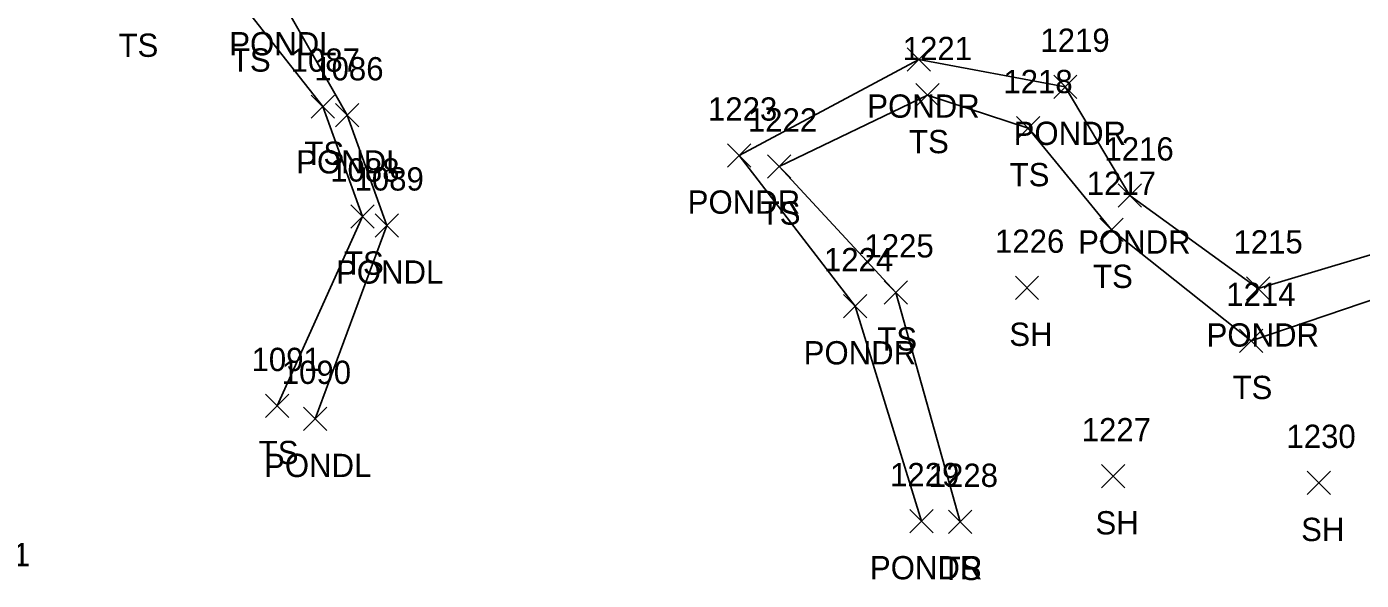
# Model space of a CAD drawing. Extents: x 1497084 to 1499861, y 734741 to 735567.
# Drawn here: x 1498306.3 to 1498420.9, y 735223.2 to 735270.8 of the extents above; entities that cross this region are included whole.
import ezdxf

# ---------------------------------------------------------------- set-up
doc = ezdxf.new("R2010")
doc.units = 0
for name, color, linetype in [('L_A', 7, 'Continuous'), ('L_I', 7, 'Continuous'), ('L_TIC', 7, 'Continuous'), ('LAWE', 7, 'Continuous'), ('LELB', 7, 'Continuous')]:
    doc.layers.add(name, color=color, linetype=linetype)

msp = doc.modelspace()

# ---------------------------------------------------------------- linework, layer by layer
at = {"layer": 'L_TIC'}
for points in [[(1498381.91, 735266.99), (1498383.91, 735268.99)], [(1498383.91, 735266.99), (1498381.91, 735268.99)], [(1498394.49, 735264.65), (1498396.49, 735266.65)], [(1498396.49, 735264.65), (1498394.49, 735266.65)], [(1498382.66, 735263.94), (1498384.66, 735265.94)], [(1498384.66, 735263.94), (1498382.66, 735265.94)], [(1498330.73, 735262.94), (1498332.73, 735264.94)], [(1498332.73, 735262.94), (1498330.73, 735264.94)], [(1498332.81, 735262.2), (1498334.81, 735264.2)], [(1498334.81, 735262.2), (1498332.81, 735264.2)], [(1498391.3, 735261.1), (1498393.3, 735263.1)], [(1498393.3, 735261.1), (1498391.3, 735263.1)], [(1498366.49, 735258.74), (1498368.49, 735260.74)], [(1498368.49, 735258.74), (1498366.49, 735260.74)], [(1498369.92, 735257.8), (1498371.92, 735259.8)], [(1498371.92, 735257.8), (1498369.92, 735259.8)], [(1498400.03, 735255.31), (1498402.03, 735257.31)], [(1498402.03, 735255.31), (1498400.03, 735257.31)], [(1498334.13, 735253.5), (1498336.13, 735255.5)], [(1498336.13, 735253.5), (1498334.13, 735255.5)], [(1498336.23, 735252.73), (1498338.23, 735254.73)], [(1498338.23, 735252.73), (1498336.23, 735254.73)], [(1498398.46, 735252.36), (1498400.46, 735254.36)], [(1498400.46, 735252.36), (1498398.46, 735254.36)], [(1498391.2, 735247.38), (1498393.2, 735249.38)], [(1498393.2, 735247.38), (1498391.2, 735249.38)], [(1498411.05, 735247.32), (1498413.05, 735249.32)], [(1498413.05, 735247.32), (1498411.05, 735249.32)], [(1498379.93, 735246.98), (1498381.93, 735248.98)], [(1498381.93, 735246.98), (1498379.93, 735248.98)], [(1498376.45, 735245.79), (1498378.45, 735247.79)], [(1498378.45, 735245.79), (1498376.45, 735247.79)], [(1498410.44, 735242.81), (1498412.44, 735244.81)], [(1498412.44, 735242.81), (1498410.44, 735244.81)], [(1498326.81, 735237.22), (1498328.81, 735239.22)], [(1498328.81, 735237.22), (1498326.81, 735239.22)], [(1498330.06, 735236.11), (1498332.06, 735238.11)], [(1498332.06, 735236.11), (1498330.06, 735238.11)], [(1498398.59, 735231.18), (1498400.59, 735233.18)], [(1498400.59, 735231.18), (1498398.59, 735233.18)], [(1498416.26, 735230.61), (1498418.26, 735232.61)], [(1498418.26, 735230.61), (1498416.26, 735232.61)], [(1498382.14, 735227.32), (1498384.14, 735229.32)], [(1498384.14, 735227.32), (1498382.14, 735229.32)], [(1498385.46, 735227.26), (1498387.46, 735229.26)], [(1498387.46, 735227.26), (1498385.46, 735229.26)]]:
    msp.add_lwpolyline(points, dxfattribs=at)
at = {"layer": 'LAWE'}
for points in [[(1498330.71, 735294.21), (1498340.7, 735295.58), (1498347.81, 735289.73), (1498355.83, 735283.8), (1498360.89, 735284.04), (1498388.96, 735276.52), (1498404.75, 735283.12), (1498435.91, 735287.74), (1498448.58, 735273.78), (1498443.34, 735255.81), (1498425.71, 735252.42), (1498412.05, 735248.32), (1498401.03, 735256.31), (1498395.49, 735265.65), (1498382.91, 735267.99), (1498367.49, 735259.74), (1498377.45, 735246.79), (1498383.14, 735228.32)], [(1498330.71, 735294.21), (1498326.26, 735287.24), (1498321.64, 735282.68), (1498317.76, 735277.18), (1498328.07, 735273.35), (1498333.81, 735263.2), (1498337.23, 735253.73), (1498331.06, 735237.11)]]:
    msp.add_lwpolyline(points, dxfattribs=at)
at = {"layer": 'LELB'}
for points in [[(1498319.31, 735283.84), (1498314.74, 735277.48), (1498315.77, 735273.22), (1498325.42, 735271.95), (1498331.73, 735263.94), (1498335.13, 735254.5), (1498327.81, 735238.22)], [(1498427.4, 735249.23), (1498411.44, 735243.81), (1498399.46, 735253.36), (1498392.3, 735262.1), (1498383.66, 735264.94), (1498370.92, 735258.8), (1498380.93, 735247.98), (1498386.46, 735228.26)]]:
    msp.add_lwpolyline(points, dxfattribs=at)

# ---------------------------------------------------------------- texts
at = {"layer": 'L_A'}
for s, p in [('TS', (1498314.18, 735268.22)), ('PONDL', (1498323.69, 735268.35)), ('TS', (1498323.83, 735266.95)), ('PONDR', (1498378.48, 735262.99)), ('TS', (1498382.07, 735259.94)), ('PONDR', (1498391.05, 735260.65)), ('TS', (1498330.14, 735258.94)), ('PONDL', (1498329.44, 735258.2)), ('TS', (1498390.71, 735257.1)), ('PONDR', (1498363.06, 735254.74)), ('TS', (1498369.33, 735253.8)), ('PONDR', (1498396.59, 735251.31)), ('TS', (1498333.54, 735249.5)), ('PONDL', (1498332.86, 735248.73)), ('TS', (1498397.87, 735248.36)), ('TS', (1498379.34, 735242.98)), ('SH', (1498390.68, 735243.38)), ('PONDR', (1498407.62, 735243.32)), ('PONDR', (1498373.02, 735241.79)), ('TS', (1498409.85, 735238.81)), ('TS', (1498326.22, 735233.22)), ('PONDL', (1498326.68, 735232.11)), ('SH', (1498398.08, 735227.18)), ('SH', (1498415.74, 735226.61)), ('PONDR', (1498378.71, 735223.32)), ('TS', (1498384.87, 735223.26))]:
    msp.add_text(s, height=2, dxfattribs=at).set_placement(p)
at = {"layer": 'L_I'}
for s, p in [('1221', (1498381.53, 735267.94)), ('1219', (1498393.35, 735268.65)), ('1087', (1498328.96, 735266.94)), ('1086', (1498330.99, 735266.2)), ('1218', (1498390.17, 735265.1)), ('1223', (1498364.8, 735262.74)), ('1222', (1498368.23, 735261.8)), ('1216', (1498398.85, 735259.31)), ('1088', (1498332.36, 735257.5)), ('1089', (1498334.45, 735256.73)), ('1217', (1498397.33, 735256.36)), ('1225', (1498378.24, 735250.98)), ('1226', (1498389.45, 735251.38)), ('1215', (1498409.93, 735251.32)), ('1224', (1498374.76, 735249.79)), ('1214', (1498409.31, 735246.81)), ('1091', (1498325.6, 735241.22)), ('1090', (1498328.2, 735240.11)), ('1227', (1498396.9, 735235.18)), ('1230', (1498414.48, 735234.61)), ('1229', (1498380.44, 735231.32)), ('1228', (1498383.76, 735231.26)), ('1061', (1498300.65, 735224.44))]:
    msp.add_text(s, height=2, dxfattribs=at).set_placement(p)

doc.saveas('drawing.dxf')
